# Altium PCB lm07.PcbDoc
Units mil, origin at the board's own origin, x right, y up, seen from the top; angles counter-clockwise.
Board outline 1215 x 1086 mil, 2 copper layers (Top, Bottom), stack 12.7 mil thick; 5 components, 21 nets, 91 pads, 69 vias.
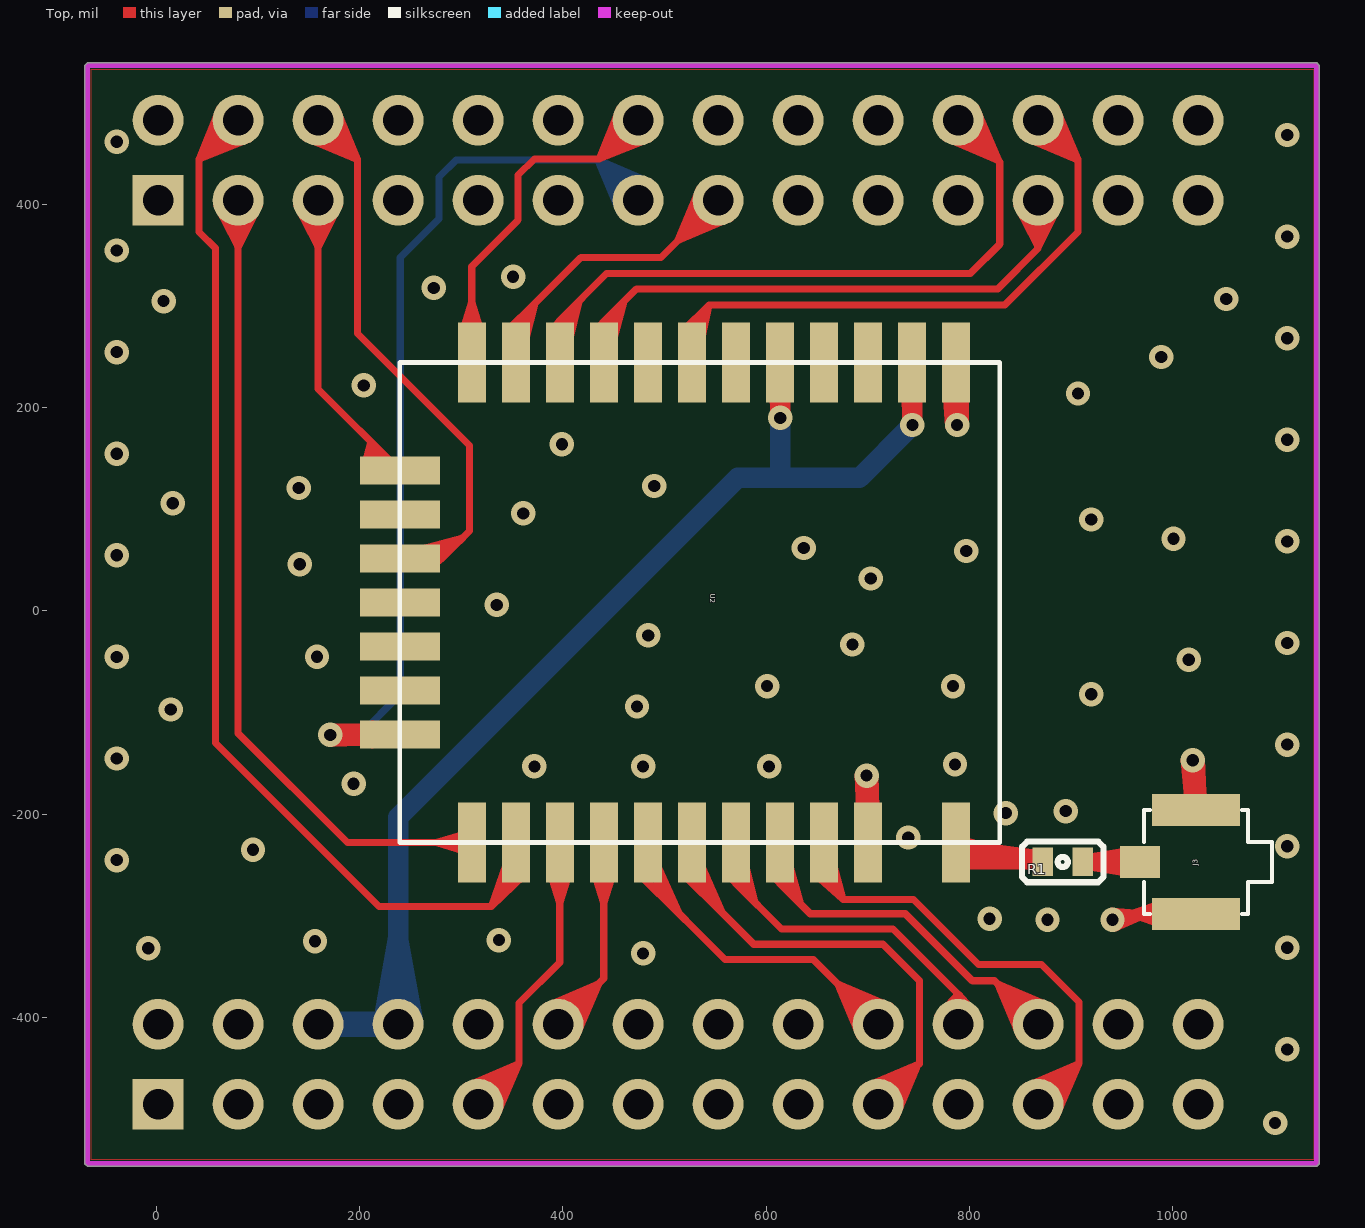
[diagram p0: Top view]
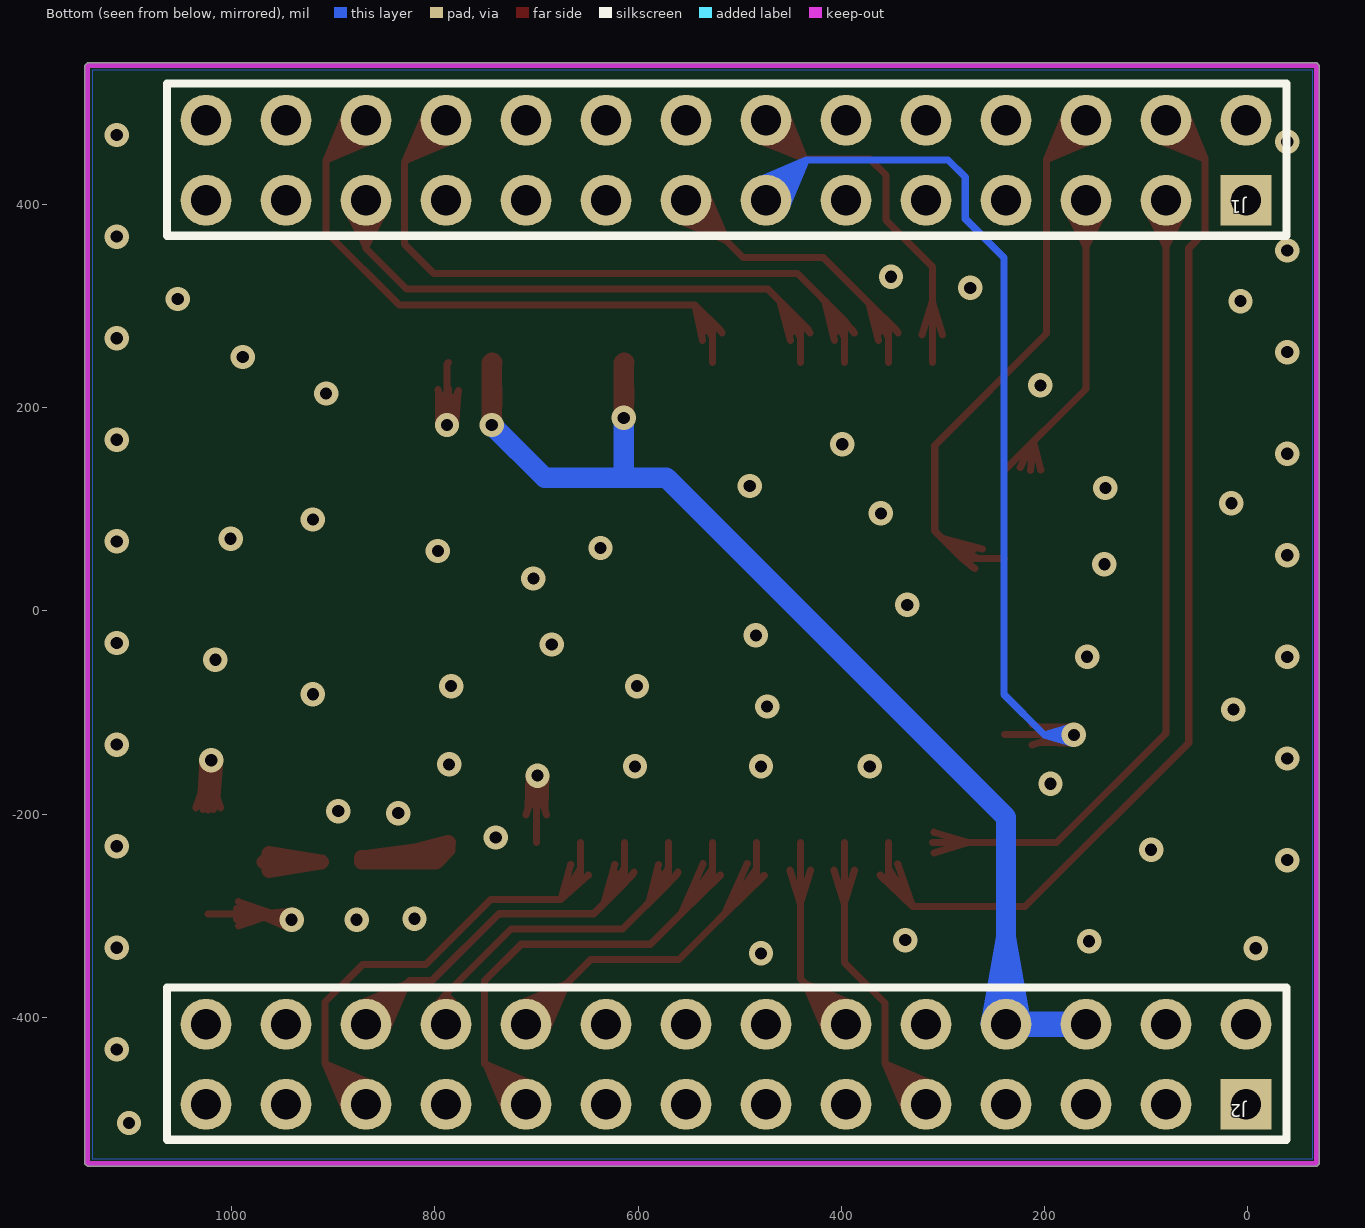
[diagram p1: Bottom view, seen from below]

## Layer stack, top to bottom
Top: signal copper 1.35
Dielectric: dielectric 10, FR-4, Dk 4.3
Bottom: signal copper 1.35

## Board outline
-70.5,-544 -68,-546.5 1142,-546.5 1144.5,-544 1144.5,537 1142,539.5 -68,539.5 -70.5,537

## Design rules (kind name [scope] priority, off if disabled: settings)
Clearance "'Default' PADS rule_15" [All] p1: gap=7
ComponentClearance "'Default' PADS rule_12" [All] p1: gap=6 collisioncheckmode=3 verticalgap=10 showdistances=FALSE
FlightTimeFalling "'Default' PADS rule_10" [All] p1: maximum=10.00
FlightTimeRising "'Default' PADS rule_9" [All] p1: maximum=10.00
Length "'Default' PADS rule_5" [All] p1: maxlimit=50000 minlimit=0
MatchedLengths "'Default' PADS rule_11" [InNetClass('All Nets')] p1: tolerance=200 checknetsindiffpair=TRUE checkdiffpairvsdiffpair=TRUE checkothers=TRUE
MaxMinImpedance "'Default' PADS rule_8" [All] p1: minimum=50.00 maximum=150.0
ParallelSegment "'Default' PADS rule_7" [All] p1: limit=1000 gap=200
ParallelSegment "'Default' PADS rule_6" [All] p2: limit=1000 gap=200
PlaneClearance "'Default' PADS rule_14" [All] p1: clearance=7
PlaneConnect "Power Plane Connect Style - pads with no thermal" [(Name='J1-7') Or (Name='J1-8') Or (Name='J1-9') Or (Name='J1-10') Or (Name='J1-11') Or (Name='J1-12') Or (Name='J1-16') Or (Name='J1-17') Or (Name='J1-18') Or (Name='J1-19') Or (Name='J1-20') Or (Name='J1-21') Or (Name='J1-25') Or (Name='J1-26') Or (Name='J2-3') Or (Name='J2-4') Or (Name='J2-5') Or (Name='J2-7') Or (Name='J2-10') Or (Name='J2-11') Or (Name='J2-13') Or (Name='J2-14') Or (Name='J2-15') Or (Name='J2-16') Or (Name='J2-17') Or (Name='J2-18') Or (Name='J2-21') Or (Name='J2-25') Or (Name='J2-26')] p1: planeconnectstyle=NoConnect reliefexpansion=20 reliefentries=4 reliefconductorwidth=10 reliefairgap=10 // PAD - No Thermal Connect Rule
PlaneConnect "Power Plane Connect Style - from global settings" [All] p2: planeconnectstyle=Relief reliefexpansion=20 reliefentries=2 reliefconductorwidth=5 reliefairgap=10
PolygonConnect [All] p1: connectstyle=Relief reliefconductorwidth=10 reliefentries=4 polygonreliefangle="90 Angle"
RoutingLayers "'Default' PADS rule_3" [All] p1: top layer_v5=TRUE bottom layer_v5=TRUE
RoutingPriority "'Default' PADS rule_2" [All] p1: routingpriority=3
RoutingTopology "'Default' PADS rule" [All] p1: topology=Shortest
RoutingVias "'Default' PADS rule_4" [All] p1: holewidth=37 width=55 viastyle="Through Hole" minholewidth=37 minwidth=55 maxholewidth=37 maxwidth=55
SilkscreenOverComponentPads [All] p1: minsilkscreentomaskgap=10
SolderMaskExpansion "Solder Mask Expansion from CAM settings" [All] p1: expansion=5
Width "'Default' PADS rule_13" [All] p1: maxlimit=50 minlimit=7 preferedwidth=7
21 further rules are at their usual default settings.

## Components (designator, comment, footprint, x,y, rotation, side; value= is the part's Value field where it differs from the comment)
J1 "CON28_2MM" CON28_2MM 1.62,404.25 r0 bottom
J2 "CON28_2MM" CON28_2MM 1.62,-485.51 r0 bottom
J3 "CON-IPEX" CON-IPEX 1023,-247 r90 top
R1 "R0402" R0402 892,-247 r0 top
U2 "MODULE_1215_1" MODULE_1215_1 239.5,244.5 r270 top

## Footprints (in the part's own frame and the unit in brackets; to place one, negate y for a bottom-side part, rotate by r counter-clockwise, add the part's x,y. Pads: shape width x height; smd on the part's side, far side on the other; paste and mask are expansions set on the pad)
CON28_2MM [mm]
  rect 1.27x1.27 hole 0.762: 1(0,0)
  round 1.27 hole 0.762: 2(0,-2) 3(2,0) 4(2,-2) 5(4,0) 6(4,-2) 7(6,0) 8(6,-2) 9(8,0) 10(8,-2) 11(10,0) 12(10,-2) 13(12,0) 14(12,-2) 15(14,0) 16(14,-2) 17(16,0) 18(16,-2) 19(18,0) 20(18,-2) 21(20,0) 22(20,-2) 23(22,0) 24(22,-2) 25(24,0) 26(24,-2) 27(26,0) 28(26,-2)
  silkscreen extent -1.02,-2.92 26.97,0.89
CON-IPEX [mm]
  rect 0.8x1 smd: 1(0,1.4)
  rect 0.8x2.2 smd: 2(-1.3,0) 3(1.3,0)
  Top pour cut-out: -1.3,1.3 1.3,1.3 1.3,-1.3 -1.3,-1.3 -1.3,1.3
  silkscreen extent -1.3,-1.9 1.3,1.3
MODULE_1215_1 [mm]
  rect 2x0.7 smd: 1(0,13.9) 2(0,12.8) 3(0,11.7) 4(0,10.6) 5(0,9.5) 6(0,8.4) 7(0,7.3) 8(0,6.2) 9(0,5.1) 10(0,4) 11(0,2.9) 12(0,1.8) 20(12,1.8) 21(12,2.9) 22(12,4) 23(12,5.1) 24(12,6.2) 25(12,7.3) 26(12,8.4) 27(12,9.5) 28(12,10.6) 29(12,11.7) 30(12,13.9)
  rect 0.7x2 smd: 13(2.7,0) 14(3.8,0) 15(4.9,0) 16(6,0) 17(7.1,0) 18(8.2,0) 19(9.3,0)
  silkscreen extent 0,0 12,15
R0402 [mil]
  rect 20x28 smd: 1(-19.69,0) 2(19.69,0)
  silkscreen extent -40,-20 40,20

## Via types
v1: diameter 24, hole 12, Top to Bottom, 69 vias

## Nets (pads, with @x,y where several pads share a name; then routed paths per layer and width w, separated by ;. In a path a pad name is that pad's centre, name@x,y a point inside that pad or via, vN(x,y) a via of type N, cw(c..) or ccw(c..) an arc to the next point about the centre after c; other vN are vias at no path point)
#RESET: J1.13 U2.19 | length 1855
  Top w7: v1@170.07,-113.55 U2.19@203.72,-114.12 ; v1@170.24,-130.47 U2.19@204.02,-129.25 ; v1@173.85,-113.99 U2.19@204.02,-129.25 ; v1@174.02,-129.95 U2.19@203.72,-114.12 ; U2.19@212.39,-131.81 v1@179.13,-121.64 ; U2.19@212.39,-111.48 v1@179.13,-121.64 ; U2.19@213.91,-121.64 v1@179.13,-121.64 ; U2.19 171,-121.64 v1(171,-122) ; v1(171,-122) U2.19@204.02,-129.25 ; v1(171,-122) U2.19@203.72,-114.12 ; v1(171,-122) U2.19@204.01,-121.64 ; v1(171,-122) U2.19@204,-121.64 ; U2.19@204.01,-121.64 172,-113.56 U2.19@204,-121.64 ; U2.19@204.01,-121.64 172.19,-130.42 U2.19@204,-121.64
  Bottom w7: v1(171,-122) 200,-122 ; v1@172.25,-130.41 200,-122 ; v1@172.25,-113.59 200,-122 ; J1.13@456.23,392.24 434.32,444 ; J1.13@462.57,395.41 434.32,444 ; J1.13@468.42,399.31 434.32,444 ; J1.13@479,409.9 434.32,444 ; J1.13@482.91,415.74 434.32,444 ; J1.13@486.08,422.08 434.32,444 ; 200,-122 240,-82 240,348 278,386 278,427 295,444 434.32,444 ; 434.32,444 J1.13 434.32,444
GND: J1.1 J1.2 J1.27 J1.28 J2.1 J2.2 J2.27 J2.28 J3.2 J3.3 U2.1 U2.29 | length 2361
  Top w7: U2.29@689.96,-200.83 v1@700.13,-167.57 ; v1@690.53,-161.24 U2.29@691.79,-194.86 ; v1@691.2,-165.37 U2.29@708.27,-194.2 ; U2.29 700.13,-163.13 v1(699,-162) ; U2.29@700.13,-202.35 v1@700.13,-167.57 ; v1@707.01,-164.86 U2.29@691.79,-194.86 ; v1@707.4,-160.7 U2.29@708.27,-194.2 ; U2.29@710.3,-200.83 v1@700.13,-167.57 ; U2.1@776.64,217.03 v1@788,184.13 ; v1@779.54,183.8 U2.1@786.85,215.99 ; v1@779.57,184.09 788,216 v1@796.43,184.09 ; v1@779.66,181.35 U2.1@777.36,214.93 ; v1@780.1,186.15 U2.1@796.32,215.34 ; U2.1@786.74,218.91 v1@788,184.13 ; U2.1 788,243.24 v1(788,183) ; v1@795.66,186.68 U2.1@777.36,214.93 ; v1@796.39,184.39 U2.1@786.85,215.99 ; v1@796.43,181.95 U2.1@796.32,215.34 ; U2.1@796.96,217.76 v1@788,184.13 ; v1@940.62,-295.51 975.75,-298.18 ; v1@943.4,-312.15 975.75,-298.18 ; J3.2@993.4,-310.26 958.69,-298.18 ; J3.2@993.4,-286.1 958.69,-298.18 ; J3.2@995.07,-303.42 958.69,-298.18 ; J3.2@995.07,-292.95 958.69,-298.18 ; J3.2@995.44,-298.18 958.69,-298.18 ; J3.3@1010.92,-193.78 1023,-159.07 ; v1@1011.52,-147.57 J3.3@1018.62,-189.52 ; v1@1011.5,-146.75 J3.3@1014.68,-182.99 ; v1@1011.7,-148.83 J3.3@1023,-180.28 ; v1@1011.9,-149.58 1025.97,-179.68 ; v1@1012.27,-150.53 1029.98,-179.14 ; J3.3@1017.77,-195.44 1023,-159.07 ; J3.2 946.82,-298.18 v1(941,-304) 975.75,-298.18 ; J3.3 1023,-150 v1(1020,-147) ; v1@1028.21,-149.22 J3.3@1014.68,-182.99 ; J3.3@1028.23,-195.44 1023,-159.07 ; v1@1028.37,-145.52 1029.98,-179.14 ; v1@1028.43,-148.12 J3.3@1018.62,-189.52 ; v1@1028.49,-147.32 J3.3@1023,-180.28 ; v1@1028.49,-146.56 1025.97,-179.68 ; J3.3@1035.08,-193.78 1023,-159.07 ; U2.29@691.79,-194.86 v1(699,-162) ; v1(699,-162) U2.29@708.27,-194.2 ; v1(699,-162) U2.29@700.13,-195.05 ; v1(699,-162) U2.29@700.13,-195.04 ; U2.29@700.13,-195.05 707.46,-162.8 U2.29@700.13,-195.04 ; U2.29@700.13,-195.05 690.61,-163.38 U2.29@700.13,-195.04 ; U2.1@777.36,214.93 v1(788,183) ; U2.1@786.85,215.99 v1(788,183) ; v1(788,183) U2.1@796.32,215.34 ; v1@1012.95,-151.75 1023,-159.07 ; v1@1012.95,-151.75 1023,-159.07 ; v1@1012.95,-151.75 1023,-159.07 ; v1@1012.95,-151.75 1023,-159.07 ; J3.3@1014.68,-182.99 v1(1020,-147) ; J3.3@1018.62,-189.52 v1(1020,-147) ; v1(1020,-147) J3.3@1023,-180.28 ; v1(1020,-147) 1023,-159.07 ; v1(1020,-147) 1029.98,-179.14 ; v1(1020,-147) 1023,-159.07 ; v1(1020,-147) 1023,-159.07 ; v1(1020,-147) 1025.97,-179.68 ; v1(1020,-147) 1023,-159.07 ; 1023,-159.07 v1@1028.45,-147.89 ; 1023,-159.07 v1@1028.45,-147.89 ; 1023,-159.07 v1@1028.45,-147.89 ; 1023,-159.07 v1@1028.45,-147.89
  other v1: 1101,-504 1113,-431.5 479,-337 -8,-332 1113,-331.5 156,-325 337,-324 877,-304 820,-303 -39,-245.18 95,-235 1113,-231.5 740,-223 836,-199 895,-197 194,-170 372,-153 479,-153 603,-153 786,-151 -39,-145.18 1113,-131.5 14,-97 473,-94 920,-82 601,-74 784,-74 1016,-48 -39,-45.18 158,-45 685,-33 1113,-31.5 484,-24 335,6 703,32 141,46 -39,54.82 797,59 637,62 1113,68.5 1001,71 920,90 361,96 16,106 140,121 490,123 -39,154.82 399,164 1113,168.5 907,214 204,222 989,250 -39,254.82 1113,268.5 7,305 1053,307 273,318 351,329 -39,354.82 1113,368.5 -39,461.82 1113,468.5
N503310: R1.1 U2.30 | length 240.8
  Top w15: 817.37,-235.9 R1.1@872.31,-243 ; U2.30 787,-228.2 787,-235 799,-247 R1.1 860.06,-247 U2.30
N503314: J3.1 R1.2 | length 213
  Top w15: J3.1@963.29,-255.22 R1.2 ; J3.1@963.29,-238.78 R1.2 ; J3.1@963.94,-247 R1.2 ; J3.1 R1.2
P0_2: J1.15 U2.11 | length 879.9
  Top w7: U2.11@345.54,276.38 372.55,302.88 ; U2.11 353.67,284 ; U2.11@363.2,266.22 372.55,302.88 ; J1.15@534.98,416.28 512.95,364.4 ; J1.15@541.32,413.1 512.95,364.4 ; J1.15@547.16,409.19 512.95,364.4 ; J1.15@557.74,398.61 512.95,364.4 ; J1.15@561.65,392.77 512.95,364.4 ; J1.15@564.83,386.43 512.95,364.4 ; U2.11@353.67,270.09 353.67,284 ; U2.11@353.67,270.09 372.55,302.88 ; U2.11@353.67,270.09 353.67,284 ; 353.67,284 417.67,348 496.55,348 J1.15 512.95,364.4 ; 353.67,284 344.12,273.89 353.67,284 ; 353.67,284 363.23,273.89 353.67,284
P0_3: J1.14 U2.12 | length 824.3
  Top w7: U2.12@300.2,271.61 310.37,304.87 ; U2.12 310.37,339 356,384.63 356,429 372,445 436.07,445 ; U2.12@310.37,270.09 310.37,304.87 ; U2.12@320.53,271.61 310.37,304.87 ; J1.14@456.13,494.85 436.07,445 ; J1.14@462.52,491.77 436.07,445 ; J1.14@468.4,487.91 436.07,445 ; J1.14@478.98,477.33 436.07,445 ; J1.14@482.84,471.45 436.07,445 ; J1.14@485.92,465.06 436.07,445 ; 436.07,445 J1.14 436.07,445
P1_0: J2.9 U2.22 | length 789.7
  Top w7: J2.9@304.56,-467.69 356.43,-445.66 ; J2.9@307.73,-474.02 356.43,-445.66 ; J2.9@311.64,-479.87 356.43,-445.66 ; J2.9@322.23,-490.45 356.43,-445.66 ; J2.9@328.07,-494.36 356.43,-445.66 ; J2.9@334.41,-497.54 356.43,-445.66 ; U2.22@386.81,-255.05 396.98,-288.31 ; U2.22@396.98,-253.53 396.98,-288.31 ; U2.22 396.98,-346 356.98,-386 356.98,-445.11 J2.9 356.43,-445.66 ; U2.22@407.15,-255.05 396.98,-288.31
P1_1: J2.12 U2.23 | length 696.3
  Top w7: J2.12@383.3,-388.95 435.17,-366.92 ; J2.12@386.47,-395.28 435.17,-366.92 ; J2.12@390.38,-401.13 435.17,-366.92 ; J2.12@400.97,-411.71 435.17,-366.92 ; J2.12@406.81,-415.62 435.17,-366.92 ; J2.12@413.15,-418.8 435.17,-366.92 ; U2.23@430.12,-255.05 440.29,-288.31 ; U2.23@440.29,-253.53 440.29,-288.31 ; U2.23 440.29,-361.81 J2.12 435.17,-366.92 ; U2.23@450.45,-255.05 440.29,-288.31
P2_0: J2.20 U2.24 | length 880.7
  Top w7: U2.24@475.76,-260.18 514.58,-297.99 ; U2.24@483.59,-253.53 514.58,-297.99 ; U2.24 483.59,-267 559.59,-343 646,-343 646.51,-343 J2.20 670.43,-366.92 ; U2.24@492.55,-248.48 514.58,-297.99 ; J2.20@692.46,-418.8 670.43,-366.92 ; J2.20@698.8,-415.62 670.43,-366.92 ; J2.20@704.64,-411.71 670.43,-366.92 ; J2.20@715.22,-401.13 670.43,-366.92 ; J2.20@719.13,-395.28 670.43,-366.92 ; J2.20@722.31,-388.95 670.43,-366.92
P2_1: J2.19 U2.25 | length 992.1
  Top w7: U2.25@519.05,-260.17 556.93,-297.03 ; U2.25@526.9,-253.53 556.93,-297.03 ; U2.25 526.9,-267 587.9,-328 715,-328 751,-364 751,-446 749.8,-446 ; U2.25@535.89,-248.54 556.93,-297.03 ; J2.19@698.29,-467.67 749.8,-446 ; J2.19@701.45,-474.02 749.8,-446 ; J2.19@705.35,-479.86 749.8,-446 ; J2.19@715.93,-490.45 749.8,-446 ; J2.19@721.78,-494.35 749.8,-446 ; J2.19@728.13,-497.51 749.8,-446 ; 749.8,-446 J2.19 749.8,-446
P2_2: J2.22 U2.26 | length 744.7
  Top w7: U2.26@562.03,-259.76 589.31,-287.1 ; U2.26 570.21,-268 ; U2.26@579.74,-249.68 589.31,-287.1 ; J2.22@768.98,-399 789.02,-377.02 ; J2.22@774.96,-403.24 789.02,-377.02 ; J2.22@781.58,-405.83 789.02,-377.02 ; J2.22@796.46,-405.83 789.02,-377.02 ; J2.22@803.09,-403.24 789.02,-377.02 ; J2.22@809.07,-399 789.02,-377.02 ; 570.21,-268 615.21,-313 725,-313 789.02,-377.02 ; 570.21,-268 579.82,-257.18 570.21,-268 ; 570.21,-268 560.6,-257.18 570.21,-268 ; 570.21,-268 U2.26@570.21,-253.53 ; 570.21,-268 U2.26@570.21,-253.53 ; U2.26@570.21,-253.53 589.31,-287.1 ; 789.02,-377.02 J2.22 789.02,-377.02
P2_4: J2.24 U2.27 | length 953.6
  Top w7: U2.27@605.37,-259.8 633.74,-288.22 ; U2.27 613.52,-268 ; U2.27@622.99,-249.53 633.74,-288.22 ; J2.24@849.94,-418.8 827.91,-366.92 ; J2.24@856.28,-415.62 827.91,-366.92 ; J2.24@862.12,-411.71 827.91,-366.92 ; J2.24@872.7,-401.13 827.91,-366.92 ; J2.24@876.61,-395.28 827.91,-366.92 ; J2.24@879.79,-388.95 827.91,-366.92 ; 613.52,-268 643.52,-298 737,-298 803,-364 824.99,-364 J2.24 827.91,-366.92 ; 613.52,-268 623.12,-257.18 613.52,-268 ; 613.52,-268 603.91,-257.18 613.52,-268 ; 613.52,-268 U2.27@613.52,-253.53 ; 613.52,-268 U2.27@613.52,-253.53 ; U2.27@613.52,-253.53 633.74,-288.22
P2_5: J2.23 U2.28 | length 957.3
  Top w7: U2.28@648.97,-260.16 675.82,-284 ; U2.28@656.82,-253.53 675.82,-284 ; U2.28 656.82,-265 675.82,-284 ; U2.28@666.23,-249.4 675.82,-284 ; J2.23@855.74,-467.69 907.61,-445.66 ; J2.23@858.91,-474.02 907.61,-445.66 ; J2.23@862.83,-479.87 907.61,-445.66 ; J2.23@873.41,-490.45 907.61,-445.66 ; J2.23@879.25,-494.36 907.61,-445.66 ; J2.23@885.59,-497.54 907.61,-445.66 ; 675.82,-284 745,-284 809,-348 871,-348 908,-385 908,-445.28 J2.23 907.61,-445.66
P3_0: J1.24 U2.7 | length 1160.4
  Top w7: U2.7@518.71,276.3 543.9,301 ; U2.7 526.9,284 ; U2.7@536.53,266.5 543.9,301 ; J1.24@855.79,465.13 907,443.76 ; J1.24@858.94,471.49 907,443.76 ; J1.24@862.83,477.34 907,443.76 ; J1.24@873.41,487.92 907,443.76 ; J1.24@879.27,491.82 907,443.76 ; J1.24@885.62,494.96 907,443.76 ; U2.7@526.9,270.09 543.9,301 ; U2.7@526.9,270.09 526.9,284 ; U2.7@526.9,270.09 526.9,284 ; 526.9,284 543.9,301 ; 526.9,284 517.35,273.89 526.9,284 ; 526.9,284 536.45,273.89 526.9,284 ; 543.9,301 835,301 907,373 907,443.76 ; 907,443.76 J1.24 907,443.76
P3_1: J1.23 U2.9 | length 1076.9
  Top w7: U2.9@432.09,276.29 460.17,304.88 ; U2.9 440.29,285 ; U2.9@449.79,266.18 460.17,304.88 ; J1.23@846.86,399.23 867.76,358.25 ; J1.23@853.44,401.97 867.76,358.25 ; J1.23@860.29,403.64 867.76,358.25 ; J1.23@875.24,403.64 867.76,358.25 ; J1.23@882.08,401.97 867.76,358.25 ; J1.23@888.67,399.23 867.76,358.25 ; U2.9@440.29,270.09 440.29,285 ; U2.9@440.29,270.09 460.17,304.88 ; U2.9@440.29,270.09 440.29,285 ; 440.29,285 472.29,317 828,317 867.76,356.76 J1.23 867.76,358.25 ; 440.29,285 430.64,273.63 440.29,285 ; 440.29,285 449.94,273.63 440.29,285
P3_2: J1.22 U2.10 | length 1253
  Top w7: U2.10@388.66,276.12 415.8,304.82 ; U2.10 396.98,286 ; U2.10@406.58,266.41 415.8,304.82 ; J1.22@777,465.17 828.87,443.14 ; J1.22@780.17,471.51 828.87,443.14 ; J1.22@784.08,477.35 828.87,443.14 ; J1.22@794.67,487.93 828.87,443.14 ; J1.22@800.51,491.84 828.87,443.14 ; J1.22@806.85,495.02 828.87,443.14 ; U2.10@396.98,270.09 396.98,286 ; U2.10@396.98,270.09 415.8,304.82 ; U2.10@396.98,270.09 396.98,286 ; 396.98,286 442.98,332 801,332 830,361 830,442.02 J1.22 828.87,443.14 ; 396.98,286 387.25,273.41 396.98,286 ; 396.98,286 406.71,273.41 396.98,286
P4_0: J1.5 U2.13 | length 707.7
  Top w7: J1.5@138.2,399.23 159.1,358.25 ; J1.5@144.78,401.97 159.1,358.25 ; J1.5@151.63,403.64 159.1,358.25 ; J1.5@166.58,403.64 159.1,358.25 ; J1.5@173.42,401.97 159.1,358.25 ; J1.5@180.01,399.23 159.1,358.25 ; U2.13@203.66,138.96 210.87,166.83 ; U2.13@213.91,138.2 210.87,166.83 ; U2.13@223.77,141.09 210.87,166.83 ; U2.13 159.1,218.6 J1.5 159.1,358.25
P4_1: J1.6 U2.15 | length 1151.6
  Top w7: J1.6@147.16,465.11 198,444.09 ; J1.6@150.29,471.48 198,444.09 ; J1.6@154.17,477.34 198,444.09 ; J1.6@164.75,487.92 198,444.09 ; J1.6@170.62,491.8 198,444.09 ; J1.6@176.98,494.93 198,444.09 ; U2.15 281,51.59 ; U2.15@261.19,61.1 301.5,72.09 ; U2.15@271.2,43.32 301.5,72.09 ; 198,444.09 198,273 308,163 308,78.59 281,51.59 ; 198,444.09 J1.6 198,444.09 ; U2.15@265.09,51.59 301.5,72.09 ; U2.15@265.09,51.59 281,51.59 ; U2.15@265.09,51.59 281,51.59 ; 281,51.59 268.41,61.31 281,51.59 ; 281,51.59 268.41,41.86 281,51.59
P4_2: J1.3 U2.20 | length 1144.7
  Top w7: J1.3@59.46,399.23 80.36,358.25 ; J1.3@66.04,401.97 80.36,358.25 ; J1.3@72.89,403.64 80.36,358.25 ; J1.3 80.36,-120.3 188,-227.94 U2.20 ; J1.3@87.84,403.64 80.36,358.25 ; J1.3@94.68,401.97 80.36,358.25 ; J1.3@101.27,399.23 80.36,358.25 ; U2.20@308.85,-238.11 275.59,-227.94 U2.20@308.85,-217.77
P4_3: J1.4 U2.21 | length 1560.1
  Top w7: J1.4@62.45,494.88 42,444.63 ; J1.4@68.83,491.78 42,444.63 ; J1.4@74.7,487.92 42,444.63 ; J1.4@85.29,477.33 42,444.63 ; J1.4@89.15,471.46 42,444.63 ; J1.4@92.25,465.08 42,444.63 ; U2.21@344.43,-249.02 329.67,-291 ; U2.21@353.67,-253.53 329.67,-291 ; U2.21 353.67,-267 329.67,-291 ; U2.21@361.63,-260.04 329.67,-291 ; 42,444.63 42,373 58,357 58,-130 219,-291 329.67,-291 ; 42,444.63 J1.4 42,444.63
VDD_BAT: J2.6 J2.8 U2.2 U2.5 | length 1753.3
  Top w20: U2.5@613.52,218.91 v1(614,190) 614,244.02 U2.5 ; U2.2@743.44,218.91 v1(744,183) 744,243.94 U2.2
  Bottom w20: J2.8@222.9,-405.45 237.84,-321.77 ; J2.8@252.78,-405.45 237.84,-321.77 ; v1(614,190) 614,131.16 ; 237.84,-321.77 J2.8 237.84,-203 572,131.16 614,131.16 ; 614,131.16 692,131.16 ; 692,131.16 743,182.16 743.16,182.16 v1(744,183) 692,131.16
  Bottom w25: J2.6 J2.8 ; J2.6 J2.8 ; J2.6 J2.8 ; J2.6 J2.8
pads on no net: J1.7 J1.8 J1.9 J1.10 J1.11 J1.12 J1.16 J1.17 J1.18 J1.19 J1.20 J1.21 J1.25 J1.26 J2.3 J2.4 J2.5 J2.7 J2.10 J2.11 J2.13 J2.14 J2.15 J2.16 J2.17 J2.18 J2.21 J2.25 J2.26 U2.3 U2.4 U2.6 U2.8 U2.14 U2.16 U2.17 U2.18

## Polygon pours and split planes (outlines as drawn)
GND on Bottom "Bottom-GND" (solid, remove dead copper, pour order 2): -64,532 1137,532 1137,-539 -64,-539
GND on Top "Top-GND" (solid, remove dead copper, pour order 4): -64,533 1139,533 1139,-540 -64,-540

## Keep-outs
Keep-Out Layer:
  lines w5: -68,-544 1142,-544 1142,537 -68,537 -68,-544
